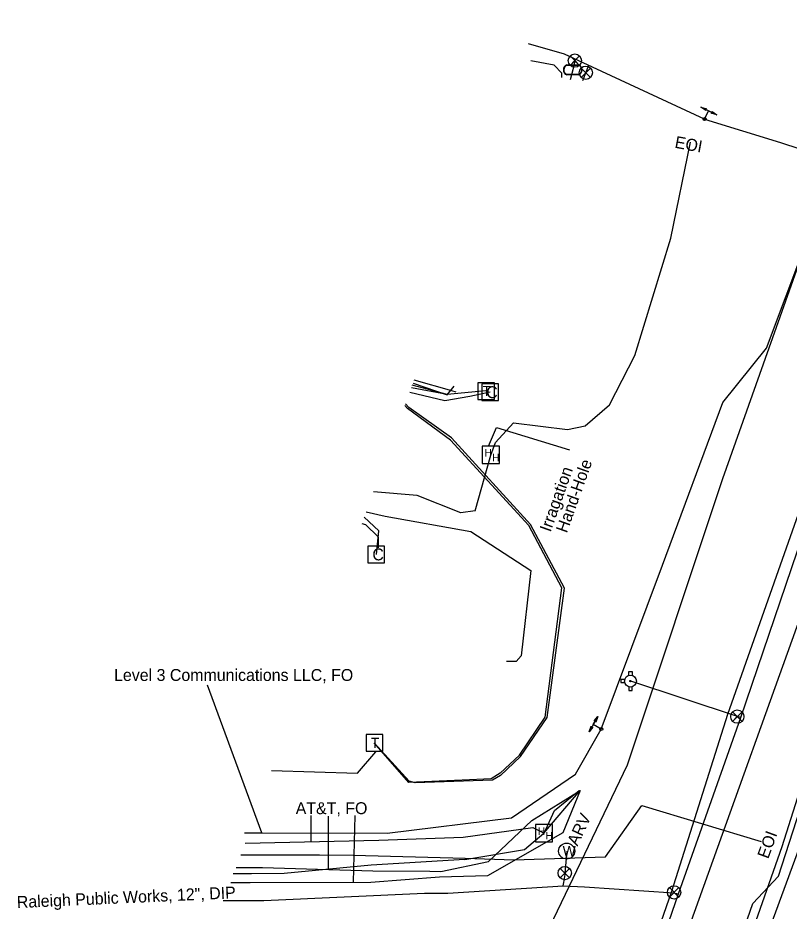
# Model space of a CAD drawing. Extents: x 2070721 to 2083039, y 729290 to 737883.
# Drawn here: x 2080782.3 to 2081041.1, y 732953.4 to 733253 of the extents above; entities that cross this region are included whole.
import ezdxf

# ---------------------------------------------------------------- set-up
doc = ezdxf.new("R2010")
doc.units = 0
for name, color, linetype in [('Cogo Default Point CELL', 7, 'Continuous'), ('COGO Default Point Elevation', 7, 'Continuous'), ('COGO Default Point Number', 7, 'Continuous'), ('Exist Utilities Gas UG Line SUE Cogo Point CELL', 7, 'Continuous'), ('Exist Utilities Gas UG Line SUE LOS B Cogo Comment', 7, 'Continuous'), ('Exist Utilities Other Unknown UG SUE LOS B Cogo Comment', 7, 'Continuous'), ('Exist Utilities Other Unknown UG SUE LOS B Cogo Elevation', 7, 'Continuous'), ('Exist Utilities Power UG Cable SUE LOS B Cogo Number', 7, 'Continuous'), ('Exist Utilities Telephone Manhole Cogo Number', 7, 'Continuous'), ('Exist Utilities Telephone UG Cable SUE LOS C Cogo Comment', 7, 'Continuous'), ('Exist Utilities Telephone UG Cable SUE LOS C Cogo Elevation', 7, 'Continuous'), ('Exist Utilities Telephone UG FO Cogo Point CELL', 7, 'Continuous'), ('Exist Utilities Telephone UG FO SUE LOS B Cogo Comment', 7, 'Continuous'), ('Exist Utilities Telephone UG FO SUE LOS B Cogo Elevation', 7, 'Continuous'), ('Exist Utilities Telephone UG FO SUE LOS B Cogo Number', 7, 'Continuous'), ('Exist Utilities TV Pedestal Cogo Elevation', 7, 'Continuous'), ('Exist Utilities TV Pedestal Cogo Number', 7, 'Continuous'), ('Exist Utilities TV UG Cable Cogo Point CELL', 7, 'Continuous'), ('Exist Utilities TV UG Cable SUE LOS C Cogo Comment', 7, 'Continuous'), ('Exist Utilities TV UG Cable SUE LOS C Cogo Elevation', 7, 'Continuous'), ('Exist Utilities TV UG Cable SUE LOS C Cogo Point CELL', 7, 'Continuous'), ('Exist Utilities TV UG FO Cable SUE LOS B Cogo Comment', 7, 'Continuous'), ('Exist Utilities TV UG FO Cable SUE LOS B Cogo Point CELL', 7, 'Continuous'), ('Exist Utilities Water Manhole Cogo Elevation', 7, 'Continuous'), ('Exist Utilities Water UG Line SUE Cogo Point CELL', 7, 'Continuous'), ('Exist Utilities Water UG Line SUE LOS B Cogo Comment', 7, 'Continuous'), ('Exist Utilities Water UG Line SUE LOS B Cogo Number', 7, 'Continuous'), ('Exist Utilities Water UG Line SUE LOS B Cogo Point CELL', 7, 'Continuous')]:
    doc.layers.add(name, color=color, linetype=linetype)

msp = doc.modelspace()

# ---------------------------------------------------------------- linework, layer by layer
at = {"layer": 'Cogo Default Point CELL'}
for p, q in [((2080940.76, 733127.44), (2080940.76, 733127.44)), ((2080902.54, 733073.03), (2080902.54, 733073.03))]:
    msp.add_line(p, q, dxfattribs=at)
for points in [[(2080937.99, 733124.67), (2080943.54, 733124.67), (2080943.54, 733130.22), (2080937.99, 733130.22), (2080937.99, 733124.67)], [(2080899.77, 733070.26), (2080905.32, 733070.26), (2080905.32, 733075.81), (2080899.77, 733075.81), (2080899.77, 733070.26)]]:
    msp.add_lwpolyline(points, dxfattribs=at)
at = {"layer": 'COGO Default Point Elevation'}
for points in [[(2080970.76, 733240.24), (2080967.61, 733237.09), (2080969.18, 733238.67), (2080970.76, 733237.09), (2080967.61, 733240.24)], [(2080974.46, 733236.18), (2080971.31, 733233.03), (2080972.89, 733234.61), (2080974.46, 733233.03), (2080971.31, 733236.18)], [(2081025.3, 733020.19), (2081022.15, 733017.04), (2081023.73, 733018.62), (2081025.3, 733017.04), (2081022.15, 733020.19)], [(2080967.38, 732967.73), (2080964.23, 732964.58), (2080965.8, 732966.15), (2080967.38, 732964.58), (2080964.23, 732967.73)], [(2081004.07, 732961.26), (2081000.92, 732958.11), (2081002.49, 732959.68), (2081004.07, 732958.11), (2081000.92, 732961.26)]]:
    msp.add_lwpolyline(points, dxfattribs=at)
for centre in [(2080969.18, 733238.67), (2080972.89, 733234.61), (2081023.73, 733018.62), (2080965.8, 732966.15), (2081002.49, 732959.68)]:
    msp.add_circle(centre, 2.23, dxfattribs=at)
at = {"layer": 'COGO Default Point Number'}
msp.add_line((2080987.87, 733030.54), (2080987.87, 733030.54), dxfattribs=at)
for points in [[(2080987.36, 733032.45), (2080987.36, 733033.74), (2080988.38, 733033.74), (2080988.38, 733032.43)], [(2080985.96, 733031.05), (2080984.67, 733031.05), (2080984.67, 733030.03), (2080985.96, 733030.03)], [(2080987.36, 733028.63), (2080987.36, 733027.34), (2080988.38, 733027.34), (2080988.38, 733028.65)]]:
    msp.add_lwpolyline(points, dxfattribs=at)
for radius in [1.98, 0.243]:
    msp.add_circle((2080987.87, 733030.54), radius, dxfattribs=at)
at = {"layer": 'Exist Utilities Other Unknown UG SUE LOS B Cogo Comment'}
msp.add_line((2080864.15, 732979.69), (2080845.85, 733029.15), dxfattribs=at)
at = {"layer": 'Exist Utilities Power UG Cable SUE LOS B Cogo Number'}
for p, q in [((2081016.89, 733220.53), (2081011.48, 733223.04)), ((2081012.75, 733219.05), (2081014.05, 733221.85)), ((2081014.05, 733221.85), (2081016.89, 733220.53)), ((2081012.75, 733219.05), (2081012.75, 733219.05))]:
    msp.add_line(p, q, dxfattribs=at)
for points in [[(2081011.48, 733223.04), (2081013.41, 733222.52), (2081012.89, 733222.38), (2081013.11, 733221.95)], [(2081016.89, 733220.53), (2081014.96, 733221.05), (2081015.49, 733221.18), (2081015.27, 733221.62)]]:
    msp.add_lwpolyline(points, close=True, dxfattribs=at)
msp.add_circle((2081012.75, 733219.05), 0.517, dxfattribs=at)
at = {"layer": 'Exist Utilities Telephone Manhole Cogo Number'}
msp.add_lwpolyline([(2080940.24, 733109.35), (2080942.86, 733115.65), (2080967.41, 733108.17)], dxfattribs=at)
at = {"layer": 'Exist Utilities Telephone UG Cable SUE LOS C Cogo Comment'}
msp.add_lwpolyline([(2080857.11, 732972.23), (2080883.47, 732972.23), (2080894.81, 732972.11), (2080932.38, 732971.19), (2080948.75, 732970.59), (2080979.46, 732971.61), (2080991.68, 732988.84), (2081031.68, 732976.69)], dxfattribs=at)
at = {"layer": 'Exist Utilities Telephone UG Cable SUE LOS C Cogo Elevation'}
msp.add_line((2080941.08, 733106.31), (2080941.08, 733106.31), dxfattribs=at)
msp.add_lwpolyline([(2080938.13, 733103.58), (2080943.88, 733103.58), (2080943.88, 733109.33), (2080938.13, 733109.33), (2080938.13, 733103.58)], dxfattribs=at)
at = {"layer": 'Exist Utilities Telephone UG FO Cogo Point CELL'}
msp.add_line((2080968.52, 733235.58), (2080968.52, 733235.58), dxfattribs=at)
for points in [[(2080966.48, 733237.28), (2080970.56, 733237.28)], [(2080966.48, 733237.15), (2080970.56, 733237.15)], [(2080970.56, 733234.02), (2080966.46, 733234.02)], [(2080970.56, 733233.88), (2080966.46, 733233.88)]]:
    msp.add_lwpolyline(points, dxfattribs=at)
for centre, radius, start, end in [((2080967.21, 733235.58), 1.86, 113.178, 245.9794), ((2080969.81, 733235.59), 1.86, 293.6483, 66.3084), ((2080967.22, 733235.58), 1.73, 115.3009, 243.7824), ((2080969.82, 733235.58), 1.73, 295.1272, 64.8728)]:
    msp.add_arc(centre, radius, start, end, dxfattribs=at)
at = {"layer": 'Exist Utilities Telephone UG FO SUE LOS B Cogo Comment'}
for p, q in [((2080939.36, 733127.86), (2080939.36, 733127.86)), ((2080901.87, 733009.84), (2080901.87, 733009.84))]:
    msp.add_line(p, q, dxfattribs=at)
for points in [[(2080936.63, 733125.03), (2080942.23, 733125.03), (2080942.23, 733130.63), (2080936.63, 733130.63), (2080936.63, 733125.03)], [(2080899.15, 733007.01), (2080904.74, 733007.01), (2080904.74, 733012.61), (2080899.15, 733012.61), (2080899.15, 733007.01)]]:
    msp.add_lwpolyline(points, dxfattribs=at)
at = {"layer": 'Exist Utilities Telephone UG FO SUE LOS B Cogo Elevation'}
msp.add_line((2080966.45, 732973.52), (2080966.45, 732973.52), dxfattribs=at)
msp.add_circle((2080966.45, 732973.52), 2.69, dxfattribs=at)
at = {"layer": 'Exist Utilities Telephone UG FO SUE LOS B Cogo Number'}
for p, q in [((2080955.99, 732982.39), (2080955.99, 732976.67)), ((2080961.71, 732982.39), (2080955.99, 732982.39)), ((2080961.71, 732976.67), (2080961.71, 732982.39)), ((2080955.99, 732976.67), (2080961.71, 732976.67)), ((2080958.85, 732979.53), (2080958.85, 732979.53))]:
    msp.add_line(p, q, dxfattribs=at)
at = {"layer": 'Exist Utilities TV Pedestal Cogo Elevation'}
for points in [[(2080968.02, 732853.09), (2080971.09, 732863.55), (2080973.36, 732870.49), (2081004.03, 732959.14), (2081024.87, 733018.36), (2081055.27, 733107.45), (2081086.77, 733195.01), (2081116.19, 733277.07), (2081135.71, 733336.57)], [(2081012.75, 733219.05), (2081038.17, 733211.25), (2081084.66, 733195.95), (2081086.52, 733195.46)], [(2081024.85, 733018.29), (2081023.77, 733018.7), (2080987.96, 733030.47)], [(2080965.26, 732961.85), (2080965.45, 732963.02), (2080966.01, 732966.32), (2080965.9, 732966.11), (2080966.57, 732973.55)], [(2080918.79, 732959.37), (2080926.6, 732959.45), (2080965.26, 732961.85)], [(2080965.26, 732961.85), (2080972.41, 732961.54), (2081002.32, 732959.56), (2081003.97, 732959.21), (2081003.97, 732959.21)], [(2080851.13, 732956.94), (2080864.81, 732956.94), (2080918.79, 732959.37)]]:
    msp.add_lwpolyline(points, dxfattribs=at)
at = {"layer": 'Exist Utilities TV Pedestal Cogo Number'}
msp.add_lwpolyline([(2080924.17, 732884.04), (2080930.33, 732882.17), (2080949.02, 732923.62), (2080986.84, 733002.49), (2081018.88, 733098.52), (2081046.79, 733177.28), (2081082.41, 733256.43), (2081124.09, 733353.56), (2081157.6, 733423.49)], dxfattribs=at)
at = {"layer": 'Exist Utilities TV UG Cable Cogo Point CELL'}
for points in [[(2080953.21, 732796.69), (2081054.09, 733077.62), (2081111.09, 733245.57), (2081176.08, 733423.78), (2081231.97, 733580.28), (2081320.16, 733847.08), (2081418.84, 734093.09), (2081467.34, 734224.03), (2081494.06, 734287.2), (2081526.74, 734352.01), (2081556, 734404.62), (2081808.13, 734757.73), (2081845.73, 734804.26), (2081874.67, 734821.58), (2081898.66, 734810.94), (2081917.15, 734795.51)], [(2080971.45, 732791.05), (2081028.93, 732955.93), (2081037.58, 732965.12), (2081059.34, 733032.5), (2081099.5, 733145.5), (2081127.24, 733222.27), (2081165.53, 733329.08), (2081197.08, 733415.76), (2081225.51, 733493.81), (2081252.34, 733568.18), (2081252.65, 733568.73)], [(2080977.85, 732787.5), (2081009.55, 732879.6), (2081045.87, 732978.13), (2081063.56, 733030.35), (2081103.18, 733143.81), (2081131.57, 733220.23), (2081172.06, 733327.38), (2081203.1, 733413.05), (2081232.13, 733491.49), (2081257.07, 733565.11), (2081257.51, 733566.68)], [(2080944.31, 732798.44), (2080951.65, 732814.71), (2080971.81, 732874.01), (2081001.7, 732960.05), (2081020.52, 733019.4), (2081051.78, 733107.87), (2081085.75, 733202.6), (2081111.57, 733279.04), (2081128.94, 733334.77), (2081148.26, 733379.04), (2081175.1, 733448.52), (2081180.53, 733478.86)], [(2080939.29, 733127.87), (2080926.33, 733126.73), (2080914.34, 733128.93)], [(2080944.24, 732998.92), (2080950.99, 733005.26), (2080959.87, 733018.3), (2080965.67, 733061.66), (2080954.33, 733083.1), (2080927.85, 733112.11), (2080913.43, 733122.3), (2080912.38, 733123.56)], [(2080944.24, 732998.92), (2080941.57, 732997.28), (2080915.55, 732996.45), (2080913.58, 732997), (2080901.87, 733009.83)]]:
    msp.add_lwpolyline(points, dxfattribs=at)
at = {"layer": 'Exist Utilities TV UG Cable SUE LOS C Cogo Comment'}
for points in [[(2080964.78, 733232.99), (2080964.78, 733234.42), (2080962.25, 733237.2), (2080954.44, 733238.62)], [(2080935.69, 733087.68), (2080940.98, 733106.38), (2080942.52, 733110.53), (2080948.63, 733117.2), (2080966.72, 733114.92), (2080972.71, 733116.12), (2080980.82, 733123.17), (2080989.3, 733139.79), (2081001.41, 733179.09), (2081008, 733211.34)], [(2080914.92, 733130.51), (2080926.37, 733126.62), (2080928.73, 733129.47)], [(2080929.38, 733127.43), (2080927.91, 733127.95), (2080915.26, 733131.44)], [(2080935.69, 733087.68), (2080930.93, 733087), (2080916.25, 733092.82), (2080901.57, 733094)], [(2080899.12, 733087.29), (2080905.51, 733085.89), (2080934.27, 733080.68), (2080954.39, 733067.67), (2080951.13, 733038.98), (2080949.52, 733037.11), (2080946.26, 733037.11)], [(2080897.68, 733083.35), (2080898.97, 733083.08), (2080903.24, 733078.92), (2080903.24, 733075.29)], [(2080867.39, 733000.52), (2080896.29, 732999.64), (2080902.38, 733006.86)], [(2080924.24, 732966.67), (2080940.22, 732970), (2080954.73, 732983.78), (2080970.95, 732993.82)], [(2080855.55, 732968), (2080864.32, 732968), (2080901.38, 732966.85), (2080920.52, 732966.81), (2080924.24, 732966.67)]]:
    msp.add_lwpolyline(points, dxfattribs=at)
at = {"layer": 'Exist Utilities TV UG Cable SUE LOS C Cogo Elevation'}
for points in [[(2080940.76, 733127.44), (2080933.93, 733126.02), (2080925.57, 733124.53), (2080913.77, 733127.35)], [(2080902.61, 733073), (2080903.41, 733080.99), (2080898.47, 733085.52)]]:
    msp.add_lwpolyline(points, dxfattribs=at)
at = {"layer": 'Exist Utilities TV UG Cable SUE LOS C Cogo Point CELL'}
for points in [[(2080974.54, 732788.58), (2081004.48, 732877.32), (2081038.77, 732975.1), (2081057.5, 733033.86), (2081097.09, 733146.25), (2081124.3, 733222.73), (2081163.35, 733330.31), (2081194.31, 733416.96), (2081222.79, 733494.92), (2081247.13, 733564.12), (2081248.81, 733567.64)], [(2080978.07, 733014.44), (2080998.67, 733069.39), (2081018.84, 733124), (2081033.47, 733142.22), (2081060.57, 733214.24)], [(2080939.29, 733127.87), (2080926.33, 733126.73), (2080914.65, 733129.77)], [(2080944.08, 732999.62), (2080950.66, 733005.65), (2080959.18, 733018.4), (2080964.82, 733061.81), (2080953.78, 733082.77), (2080927.47, 733111.31), (2080913.03, 733121.96), (2080912.17, 733123)], [(2080944.08, 732999.62), (2080941.08, 732997.75), (2080931.36, 732997.26), (2080913.5, 732996.51), (2080901.87, 733009.84)], [(2080970.95, 732993.82), (2080965.18, 732979.6), (2080939.85, 732965.21), (2080923.77, 732964.8), (2080900.75, 732963)], [(2080932.27, 732970.74), (2080952.25, 732974.02), (2080958.82, 732979.51), (2080970.96, 732993.81)], [(2080958.85, 732979.53), (2080962.37, 732987.19), (2080970.68, 732993.79)], [(2080958.85, 732979.53), (2080962.37, 732987.19), (2080970.68, 732993.79)], [(2080858.5, 732976.22), (2080903.44, 732977.24), (2080931.69, 732978.16), (2080955.04, 732981.38), (2080958.85, 732979.53)], [(2080932.27, 732970.74), (2080900.87, 732968.8), (2080871.59, 732966.01), (2080860.69, 732965.93), (2080854.53, 732965.93)], [(2080900.75, 732963), (2080860.26, 732962.85), (2080853.71, 732962.85)], [(2080900.75, 732963), (2080860.26, 732962.85), (2080853.71, 732962.85)]]:
    msp.add_lwpolyline(points, dxfattribs=at)
at = {"layer": 'Exist Utilities Water Manhole Cogo Elevation'}
for p, q in [((2080880.72, 732976.79), (2080880.72, 732985.51)), ((2080886.46, 732967.46), (2080886.46, 732985.19)), ((2080894.89, 732963.09), (2080895.51, 732985.5))]:
    msp.add_line(p, q, dxfattribs=at)
at = {"layer": 'Exist Utilities Water UG Line SUE Cogo Point CELL'}
for p, q in [((2080976.94, 733018.69), (2080973.99, 733013.51)), ((2080975.39, 733015.97), (2080976.94, 733018.69)), ((2080978.07, 733014.44), (2080975.39, 733015.97)), ((2080978.07, 733014.44), (2080978.07, 733014.44))]:
    msp.add_line(p, q, dxfattribs=at)
for points in [[(2080976.94, 733018.69), (2080976.27, 733016.81), (2080976.18, 733017.35), (2080975.72, 733017.17)], [(2080973.99, 733013.51), (2080974.67, 733015.4), (2080974.76, 733014.86), (2080975.21, 733015.04)]]:
    msp.add_lwpolyline(points, close=True, dxfattribs=at)
msp.add_circle((2080978.07, 733014.44), 0.517, dxfattribs=at)
at = {"layer": 'Exist Utilities Water UG Line SUE LOS B Cogo Number'}
msp.add_lwpolyline([(2080858.37, 732979.69), (2080864.15, 732979.69), (2080906.18, 732979.56), (2080947.92, 732984.72), (2080969.41, 732999.27), (2080978.07, 733014.44)], dxfattribs=at)
at = {"layer": 'Exist Utilities Water UG Line SUE LOS B Cogo Point CELL'}
for p, q in [((2080969.33, 733239.15), (2080968.52, 733235.58)), ((2080968.52, 733235.58), (2080967.64, 733232.28)), ((2080973.8, 733237.05), (2080971.75, 733231.84))]:
    msp.add_line(p, q, dxfattribs=at)
msp.add_lwpolyline([(2081012.75, 733219.05), (2080965.74, 733240.78), (2080953.65, 733244.3)], dxfattribs=at)

# ---------------------------------------------------------------- texts
at = {"layer": 'Cogo Default Point CELL'}
for p in [(2080939.46, 733125.44), (2080901.24, 733071.03)]:
    msp.add_text('C', height=4, dxfattribs=at).set_placement(p)
at = {"layer": 'Exist Utilities Gas UG Line SUE Cogo Point CELL'}
msp.add_text('Raleigh Public Works, 12", DIP', height=4, rotation=2.5774, dxfattribs=at).set_placement((2080781.99, 732954.39))
at = {"layer": 'Exist Utilities Gas UG Line SUE LOS B Cogo Comment'}
msp.add_text('AT&T, FO', height=4, dxfattribs=at).set_placement((2080875.51, 732985.91))
at = {"layer": 'Exist Utilities Other Unknown UG SUE LOS B Cogo Elevation'}
msp.add_text('Level 3 Communications LLC, FO', height=4, dxfattribs=at).set_placement((2080814.54, 733030.59))
at = {"layer": 'Exist Utilities Telephone UG Cable SUE LOS C Cogo Elevation'}
for p in [(2080938.92, 733105.84), (2080941.48, 733104.31)]:
    msp.add_text('H', height=2.5, dxfattribs=at).set_placement(p)
at = {"layer": 'Exist Utilities Telephone UG FO SUE LOS B Cogo Comment'}
for p in [(2080938.23, 733126.14), (2080900.74, 733008.13)]:
    msp.add_text('T', height=3.42, dxfattribs=at).set_placement(p)
at = {"layer": 'Exist Utilities Telephone UG FO SUE LOS B Cogo Elevation'}
msp.add_text('W', height=3.5, dxfattribs=at).set_placement((2080965.1, 732971.77))
at = {"layer": 'Exist Utilities Telephone UG FO SUE LOS B Cogo Number'}
for p in [(2080956.76, 732978.94), (2080959.34, 732977.47)]:
    msp.add_text('H', height=2.5, dxfattribs=at).set_placement(p)
at = {"layer": 'Exist Utilities TV UG FO Cable SUE LOS B Cogo Comment'}
msp.add_text('EOI', height=4, rotation=69.9399, dxfattribs=at).set_placement((2081034.08, 732970.69))
at = {"layer": 'Exist Utilities TV UG FO Cable SUE LOS B Cogo Point CELL'}
msp.add_text('ARV', height=4, rotation=64.6909, dxfattribs=at).set_placement((2080970.06, 732974.98))
at = {"layer": 'Exist Utilities Water UG Line SUE LOS B Cogo Comment'}
for s, rotation, p in [('EOI', 349.5989, (2081002.52, 733209.48)), ('Hand-Hole', 70.368, (2080966.5, 733079.99)), ('Irragation ', 70.368, (2080961.03, 733080.3))]:
    msp.add_text(s, height=4, rotation=rotation, dxfattribs=at).set_placement(p)

doc.saveas('drawing.dxf')
